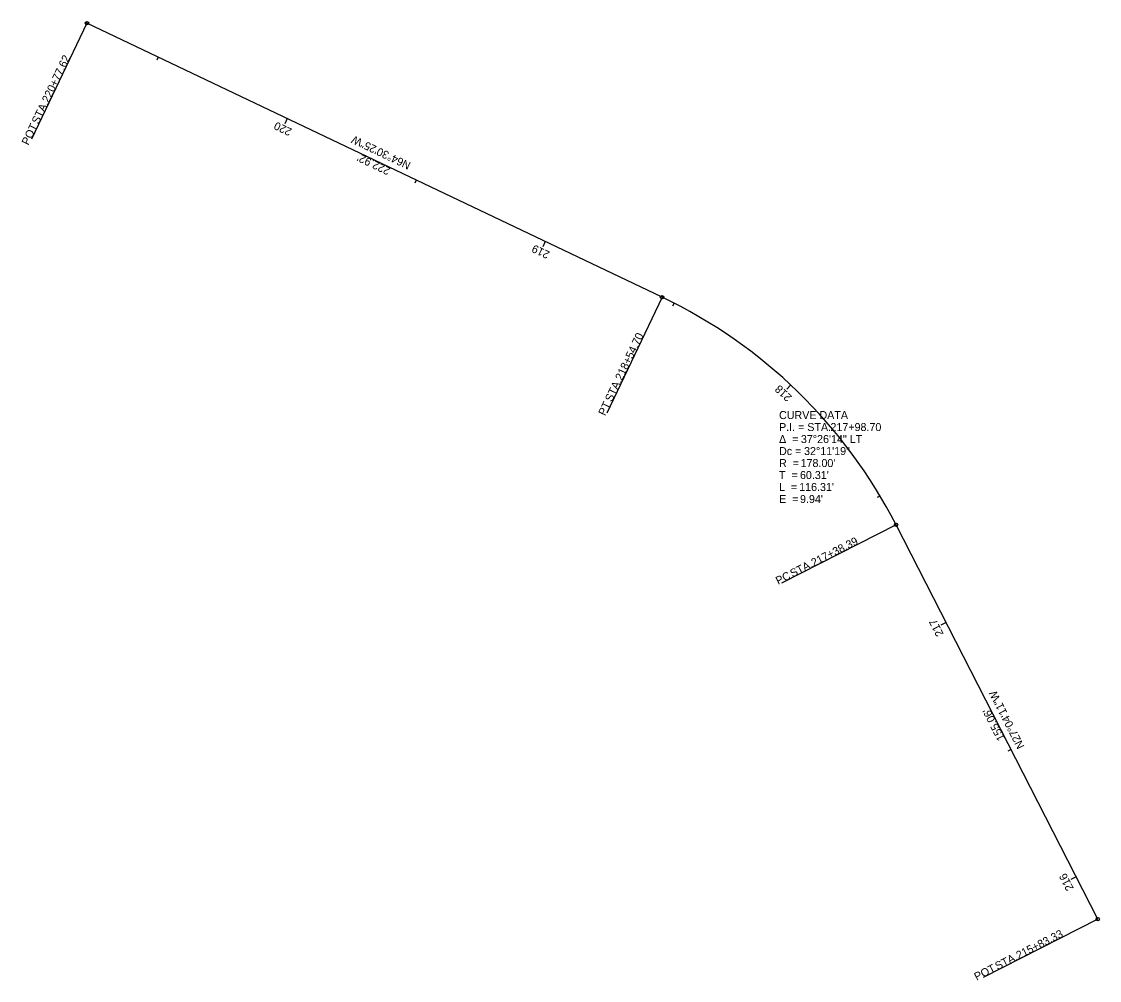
# Model space of a CAD drawing. Extents: x 186425 to 186802, y 352638 to 352973.
import ezdxf

# ---------------------------------------------------------------- set-up
doc = ezdxf.new("R2010")
doc.units = 0
for name, color, linetype in [('GE_X_Alignment', 7, 'Continuous'), ('GE_X_Alignment_100_Bearings', 7, 'Continuous'), ('GE_X_Alignment_100_Cardinal_Points', 7, 'Continuous'), ('GE_X_Alignment_100_Curve_Data', 7, 'Continuous'), ('GE_X_Alignment_100_Distances', 7, 'Continuous'), ('GE_X_Alignment_100_Stations', 7, 'Continuous')]:
    doc.layers.add(name, color=color, linetype=linetype)

msp = doc.modelspace()

# ---------------------------------------------------------------- linework, layer by layer
at = {"layer": 'GE_X_Alignment'}
for p, q in [((186648.86, 352876.81), (186447.64, 352972.75)), ((186801.31, 352659.07), (186730.75, 352797.14))]:
    msp.add_line(p, q, dxfattribs=at)
msp.add_arc((186572.24, 352716.14), 178, 27.0696, 64.5068, dxfattribs=at)
at = {"layer": 'GE_X_Alignment_100_Cardinal_Points'}
for p, q in [((186447.64, 352972.75), (186428.27, 352932.13)), ((186648.86, 352876.81), (186629.49, 352836.19)), ((186730.75, 352797.14), (186690.68, 352776.66)), ((186801.31, 352659.07), (186761.24, 352638.59))]:
    msp.add_line(p, q, dxfattribs=at)
for centre in [(186447.64, 352972.75), (186648.86, 352876.81), (186730.75, 352797.14), (186801.31, 352659.07)]:
    msp.add_circle(centre, 0.6, dxfattribs=at)
at = {"layer": 'GE_X_Alignment_100_Stations'}
for p, q in [((186472.57, 352960.87), (186472.05, 352959.78)), ((186517.7, 352939.35), (186516.84, 352937.54)), ((186562.83, 352917.82), (186562.32, 352916.74)), ((186607.96, 352896.3), (186607.1, 352894.5)), ((186653.07, 352874.73), (186652.52, 352873.66)), ((186693.87, 352846.11), (186692.5, 352844.65)), ((186725.13, 352807.3), (186724.1, 352806.68)), ((186748.22, 352762.95), (186746.44, 352762.04)), ((186770.97, 352718.43), (186769.9, 352717.89)), ((186793.72, 352673.91), (186791.94, 352673))]:
    msp.add_line(p, q, dxfattribs=at)

# ---------------------------------------------------------------- texts
at = {"layer": 'GE_X_Alignment_100_Bearings'}
for s, rotation, p in [('N64°30\'25"W', 154.5068, (186561.17, 352923.93)), ('N27°04\'11"W', 117.0696, (186775.78, 352719.57))]:
    msp.add_text(s, height=2.8, rotation=rotation, dxfattribs=at).set_placement(p)
at = {"layer": 'GE_X_Alignment_100_Cardinal_Points'}
for s, rotation, p in [('220+77.62', 64.5068, (186434.23, 352944.7)), (' STA. ', 64.5068, (186430.21, 352936.29)), ('POT', 64.5068, (186427.14, 352929.85)), ('218+54.70', 64.5068, (186634.82, 352847.45)), (' STA. ', 64.5068, (186630.81, 352839.04)), ('PT', 64.5068, (186628.93, 352835.11)), ('217+38.39', 27.0696, (186701.9, 352782.44)), (' STA. ', 27.0696, (186693.6, 352778.2)), ('PC', 27.0696, (186689.51, 352776.1)), ('215+83.33', 27.0696, (186773.62, 352644.95)), (' STA. ', 27.0696, (186765.32, 352640.71)), ('POT', 27.0696, (186758.97, 352637.47))]:
    msp.add_text(s, height=2.8, rotation=rotation, dxfattribs=at).set_placement(p)
at = {"layer": 'GE_X_Alignment_100_Curve_Data'}
for s, p in [('CURVE DATA', (186689.8, 352834.17)), ('P.I. = STA. ', (186689.8, 352829.97)), ('217+98.70', (186707.79, 352829.97)), ('Δ  = ', (186689.8, 352825.77)), ('37°26\'14" LT', (186697.45, 352825.77)), ('Dc = ', (186689.8, 352821.57)), ('32°11\'19"', (186698.55, 352821.57)), ('R  = ', (186689.8, 352817.37)), ("178.00'", (186697.34, 352817.37)), ('T  = ', (186689.8, 352813.17)), ("60.31'", (186697.12, 352813.17)), ('L  = ', (186689.8, 352808.97)), ("116.31'", (186696.84, 352808.97)), ('E  = ', (186689.8, 352804.77)), ("9.94'", (186697.14, 352804.77))]:
    msp.add_text(s, height=2.8, dxfattribs=at).set_placement(p)
at = {"layer": 'GE_X_Alignment_100_Distances'}
for s, rotation, p in [("222.92'", 154.5068, (186554.04, 352921.97)), ("155.06'", 117.0696, (186768.92, 352722.35))]:
    msp.add_text(s, height=2.8, rotation=rotation, dxfattribs=at).set_placement(p)
at = {"layer": 'GE_X_Alignment_100_Stations'}
for s, rotation, p in [('220', 154.5068, (186519.57, 352935.68)), ('219', 154.5068, (186609.8, 352892.66)), ('218', 136.901, (186694.53, 352842.06)), ('217', 117.0696, (186747.47, 352758.93)), ('216', 117.0696, (186792.98, 352669.87))]:
    msp.add_text(s, height=2.8, rotation=rotation, dxfattribs=at).set_placement(p)

doc.saveas('drawing.dxf')
